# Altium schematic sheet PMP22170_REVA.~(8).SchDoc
size 431 x 279 mm; Date: Not shown in title block; ApprovedBy: Not shown in title block; CheckedBy: Not shown in title block; Author: Not shown in title block; CompanyName: Not shown in title block; Engineer: Not shown in title block; Organization: Not shown in title block; Address1: Not shown in title block; Address2: Not shown in title block; Address3: Not shown in title block; Address4: Not shown in title block; DocumentNumber: 1; Revision: Use project parameter SCH_Rev; SheetNumber: 1; SheetTotal: 1; PageSetup: Record=PageOptions¦CenterHorizontal=True¦CenterVertical=True¦PrintScale=1.00¦XCorrection=1.00¦YCorrection=1.00¦PrintKind=0¦BorderSize=5000000¦LeftOffset=0¦BottomOffset=0¦Orientation=2¦PaperLength=1000¦PaperWidth=1000¦Scale=100¦PaperSource=15¦PrintQuality=600¦MediaType=1¦DitherType=10¦PaperKind=Letter¦PrintScaleMode=1
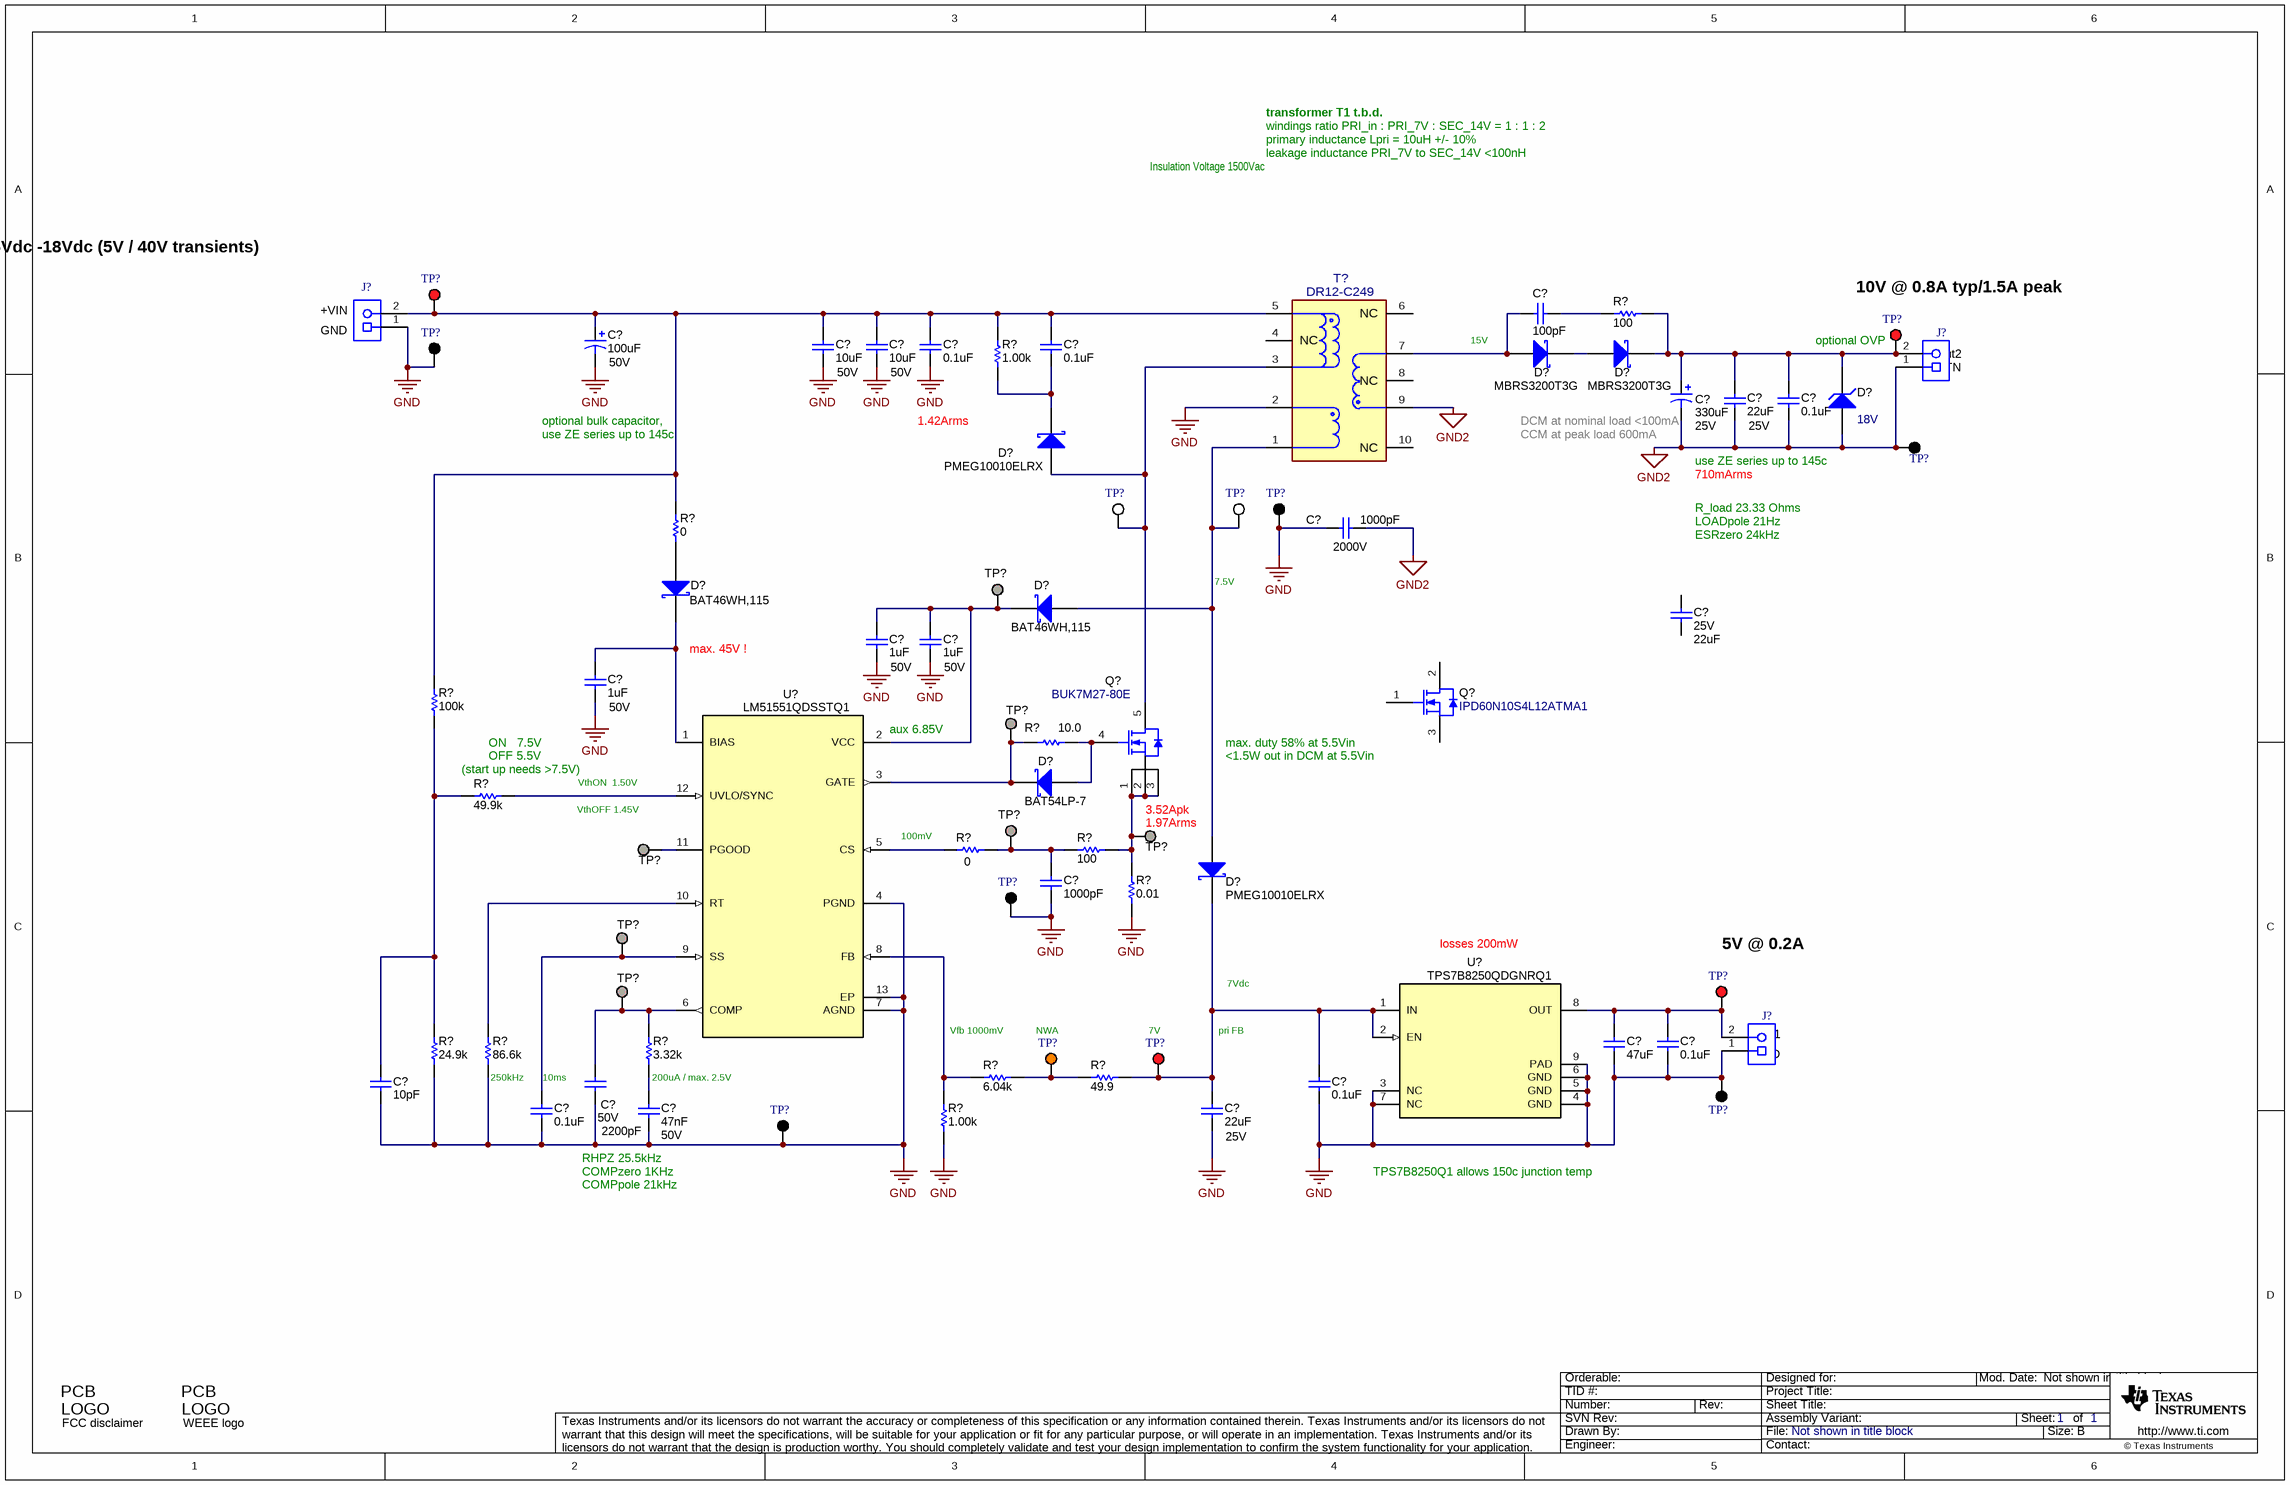
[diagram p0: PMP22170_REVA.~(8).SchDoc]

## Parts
(Parts that share a designator on the sheet are numbered #1, #2 ... from top to bottom, then left to right.)
C?#1  ValueDisplayed: 100pF  [0805_HV]  (hidden comment: Capacitor)
C?#2  ValueDisplayed: 100uF  Value2: 50V  [Panasonic_G]  (hidden comment: Cap_Polarized)
C?#3  ValueDisplayed: 10uF  Value2: 50V  [1210_270]  (hidden comment: Capacitor)
C?#4  ValueDisplayed: 10uF  Value2: 50V  [1210_270]  (hidden comment: Capacitor)
C?#5  ValueDisplayed: 0.1uF  [0603]  (hidden comment: Capacitor)
C?#6  ValueDisplayed: 0.1uF  [0603]  (hidden comment: Capacitor)
C?#7  ValueDisplayed: 330uF  Value2: 25V  [SM_RADIAL_10BMM]  (hidden comment: Cap_Polarized)
C?#8  ValueDisplayed: 22uF  Value2: 25V  [1210_270]  (hidden comment: Capacitor)
C?#9  ValueDisplayed: 0.1uF  [0603]  (hidden comment: Capacitor)
C?#10  ValueDisplayed: 1000pF  Value2: 2000V  [1808]  (hidden comment: Capacitor)
C?#11  VDC_V: 25V  ValueDisplayed: 22uF  [1210_270]  (hidden comment: TMK325B7226KMHT)
C?#12  ValueDisplayed: 1uF  Value2: 50V  [0805_HV1]  (hidden comment: Capacitor)
C?#13  ValueDisplayed: 1uF  Value2: 50V  [0805_HV1]  (hidden comment: Capacitor)
C?#14  ValueDisplayed: 1uF  Value2: 50V  [0805_HV1]  (hidden comment: Capacitor)
C?#15  ValueDisplayed: 1000pF  [0603]  (hidden comment: Capacitor)
C?#16  ValueDisplayed: 47uF  [1210_270]  (hidden comment: Capacitor)
C?#17  ValueDisplayed: 0.1uF  [0603]  (hidden comment: Capacitor)
C?#18  ValueDisplayed: 10pF  [0603]  (hidden comment: Capacitor)
C?#19  VDC_V: 50V  ValueDisplayed: 2200pF  [0603]  (hidden comment: GRM188R61H222KA01D)
C?#20  ValueDisplayed: 0.1uF  [0603]  (hidden comment: Capacitor)
C?#21  ValueDisplayed: 0.1uF  [0603]  (hidden comment: Capacitor)
C?#22  Cap_F: 47nF  VDC_V: 50V  [0603]  (hidden comment: CGA3E2X7R1H473K080AA)
C?#23  ValueDisplayed: 22uF  Value2: 25V  [1210_270]  (hidden comment: Capacitor)
D?#1  PartNumber: MBRS3200T3G  [SMB]  (hidden comment: DIODE_SCHOTTKY)
D?#2  PartNumber: MBRS3200T3G  [SMB]  (hidden comment: DIODE_SCHOTTKY)
D?#3  value 18V  [SOD-123]  (hidden comment: Zener)
D?#4  PartNumber: PMEG10010ELRX  [SOD-123W]  (hidden comment: DIODE_SCHOTTKY)
D?#5  PartNumber: BAT46WH,115  [SOD-123F]  (hidden comment: DIODE_SCHOTTKY)
D?#6  PartNumber: BAT46WH,115  [SOD-123F]  (hidden comment: DIODE_SCHOTTKY)
D?#7  PartNumber: BAT54LP-7  [X1-DFN1006-2]  (hidden comment: DIODE_SCHOTTKY)
D?#8  PartNumber: PMEG10010ELRX  [SOD-123W]  (hidden comment: DIODE_SCHOTTKY)
J?#1  Receptacle_2x1  [TERM_BLK_ED555-2DS]  (value not drawn)
J?#2  Receptacle_2x1  [TERM_BLK_ED555-2DS]  (value not drawn)
J?#3  Receptacle_2x1  [TERM_BLK_ED555-2DS]  (value not drawn)
Logo?#1  FCC disclaimer  [FCC_disclaimer]  (no BOM)
Logo?#2  WEEE logo  [WEEE_Minimum]  (no BOM)
Q?#1  IPD60N10S4L12ATMA1  [DPAK]
Q?#2  BUK7M27-80E  [LFPAK33]
R?#1  ValueDisplayed: 100  [0805_HV]  (hidden comment: Resistor)
R?#2  ValueDisplayed: 1.00k  [1210]  (hidden comment: ERJ14NF1001U)
R?#3  ValueDisplayed: 0  [0603]  (hidden comment: Resistor)
R?#4  ValueDisplayed: 100k  [0603]  (hidden comment: CRCW0603100KFKEA)
R?#5  ValueDisplayed: 10.0  [0603]  (hidden comment: Resistor)
R?#6  ValueDisplayed: 49.9k  [0603]  (hidden comment: CRCW060349K9FKEA)
R?#7  ValueDisplayed: 0  [0603]  (hidden comment: Resistor)
R?#8  ValueDisplayed: 100  [0603]  (hidden comment: Resistor)
R?#9  ValueDisplayed: 0.01  [0612]  (hidden comment: ERJ-B2CFR01V)
R?#10  ValueDisplayed: 24.9k  [0603]  (hidden comment: CRCW060324K9FKEA)
R?#11  ValueDisplayed: 86.6k  [0603]  (hidden comment: Resistor)
R?#12  ValueDisplayed: 3.32k  [0603]  (hidden comment: CRCW06033K32FKEA)
R?#13  ValueDisplayed: 6.04k  [0603]  (hidden comment: Resistor)
R?#14  ValueDisplayed: 49.9  [0603]  (hidden comment: Resistor)
R?#15  ValueDisplayed: 1.00k  [0603]  (hidden comment: Resistor)
T?  DR12-C249  [FP-DR12-C249_SMT_12MM0_14MM5-MFG]
TP?#1  5000  [Keystone5000]  (value not drawn)
TP?#2  5000  [Keystone5000]  (value not drawn)
TP?#3  5001  [Keystone5001]  (value not drawn)
TP?#4  5001  [Keystone5001]  (value not drawn)
TP?#5  5002  [Keystone5002]  (value not drawn)
TP?#6  5002  [Keystone5002]  (value not drawn)
TP?#7  5001  [Keystone5001]  (value not drawn)
TP?#8  TP_SM_1MM  [TP_SM_1MM]  (value not drawn)  (no BOM)
TP?#9  TP_SM_1MM  [TP_SM_1MM]  (value not drawn)  (no BOM)
TP?#10  TP_SM_1MM  [TP_SM_1MM]  (value not drawn)  (no BOM)
TP?#11  TP_SM_1MM  [TP_SM_1MM]  (value not drawn)  (no BOM)
TP?#12  TP_SM_1MM  [TP_SM_1MM]  (value not drawn)  (no BOM)
TP?#13  5001  [Keystone5001]  (value not drawn)
TP?#14  TP_SM_1MM  [TP_SM_1MM]  (value not drawn)  (no BOM)
TP?#15  TP_SM_1MM  [TP_SM_1MM]  (value not drawn)  (no BOM)
TP?#16  5000  [Keystone5000]  (value not drawn)
TP?#17  5003  [Keystone5003]  (value not drawn)
TP?#18  5000  [Keystone5000]  (value not drawn)
TP?#19  5001  [Keystone5001]  (value not drawn)
TP?#20  5001  [Keystone5001]  (value not drawn)
U?#1  LM51551QDSSTQ1  [DSS0012C]
U?#2  TPS7B8250QDGNRQ1  [DGN0008D_N]

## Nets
GND: C?#2.2(-) C?#3.2 C?#4.2 C?#5.2 C?#10.2 C?#12.2 C?#13.2 C?#14.2 C?#15.2 C?#16.2 C?#17.2 C?#18.2 C?#19.2 C?#20.2 C?#21.2 C?#22.2 C?#23.2 J?#1.1 J?#3.1 R?#9.1 R?#10.1 R?#11.1 R?#15.2 T?.2(S3) TP?#3.1 TP?#7.1 TP?#13.1 TP?#19.1 TP?#20.1 U?#1.4(PGND) U?#1.7(AGND) U?#1.13(EP) U?#2.3(NC) U?#2.4(GND) U?#2.5(GND) U?#2.6(GND) U?#2.7(NC) U?#2.9(PAD)
GND2: C?#7.2(-) C?#8.2 C?#9.2 C?#10.1 D?#3.2(A) J?#2.1 T?.9(S4) TP?#4.1
NetC?#1_1: C?#1.1 R?#1.1
NetC?#1_2: C?#1.2 D?#1.2(A) T?.7
NetC?#2_1: C?#2.1(+) C?#3.1 C?#4.1 C?#5.1 C?#6.1 J?#1.2 R?#2.2 R?#3.2 R?#4.2 T?.5(S1,S2) TP?#1.1
NetC?#6_2: C?#6.2 D?#4.1(K) R?#2.1
NetC?#7_1: C?#7.1(+) C?#8.1 C?#9.1 D?#2.1(K) D?#3.1(K) J?#2.2 R?#1.2 TP?#2.1
NetC?#12_1: C?#12.1 C?#13.1 D?#6.1(K) TP?#8.1 U?#1.2(VCC)
NetC?#14_1: C?#14.1 D?#5.1(K) U?#1.1(BIAS)
NetC?#15_1: C?#15.1 R?#7.2 R?#8.1 TP?#10.1
NetC?#16_1: C?#16.1 C?#17.1 J?#3.2 TP?#16.1 U?#2.8(OUT)
NetC?#18_1: C?#18.1 R?#4.1 R?#6.1 R?#10.2
NetC?#19_1: C?#19.1 R?#12.2 TP?#15.1 U?#1.6(COMP)
NetC?#20_1: C?#20.1 C?#23.1 D?#8.1(K) R?#14.2 TP?#18.1 U?#2.1(IN) U?#2.2(EN)
NetC?#21_1: C?#21.1 TP?#14.1 U?#1.9(SS)
NetC?#22_1: C?#22.1 R?#12.1
NetD?#1_1: D?#1.1(K) D?#2.2(A)
NetD?#4_2: D?#4.2(A) Q?#2.5(D) T?.3 TP?#5.1
NetD?#5_2: D?#5.2(A) R?#3.1
NetD?#6_2: D?#6.2(A) D?#8.2(A) T?.1 TP?#6.1
NetD?#7_1: D?#7.1(K) R?#5.1 TP?#9.1 U?#1.3(GATE)
NetD?#7_2: D?#7.2(A) Q?#2.4(G) R?#5.2
NetQ?#2_1: Q?#2.1(S) Q?#2.2(S) Q?#2.3(S) R?#8.2 R?#9.2 TP?#11.1
NetR?#6_2: R?#6.2 U?#1.12(UVLO/SYNC)
NetR?#7_1: R?#7.1 U?#1.5(CS)
NetR?#11_2: R?#11.2 U?#1.10(RT)
NetR?#13_1: R?#13.1 R?#14.1 TP?#17.1
NetR?#13_2: R?#13.2 R?#15.1 U?#1.8(FB)
NetTP?#12_1: TP?#12.1 U?#1.11(PGOOD)

Not connected (* = marked no-connect by the designer): C?#11 1 2; Q?#1 1(G) 2(D) 3(S); T? 4(NC) 6(NC) 8(NC) 10(NC)

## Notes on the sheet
- Insulation Voltage 1500Vac
- windings ratio PRI_in : PRI_7V : SEC_14V = 1 : 1 : 2
- primary inductance Lpri = 10uH +/- 10%
- leakage inductance PRI_7V to SEC_14V <100nH
- transformer T1 t.b.d.
- Input 6Vdc -18Vdc (5V / 40V transients)
- 10V @ 0.8A typ/1.5A peak
- (near J?#1) +VIN
- (near J?#1) GND
- 15V
- (near TP?#2) optional OVP
- (near J?#2) Vout2
- (near J?#2) RTN
- optional bulk capacitor,
- use ZE series up to 145c
- 1.42Arms
- (near C?#7) CCM at peak load 600mA
- (near C?#7) DCM at nominal load <100mA
- (near C?#9) use ZE series up to 145c
- 710mArms
- R_load 23.33 Ohms
- LOADpole 21Hz
- ESRzero 24kHz
- 7.5V
- (near D?#5) max. 45V !
- (near R?#6) (start up needs >7.5V)
- (near R?#6) ON   7.5V
- (near R?#6) OFF 5.5V
- (near U?#1) aux 6.85V
- (near Q?#1) max. duty 58% at 5.5Vin
- (near Q?#1) <1.5W out in DCM at 5.5Vin
- VthON  1.50V
- (near TP?#12) VthOFF 1.45V
- 100mV
- 3.52Apk
- (near TP?#11) 1.97Arms
- losses 200mW
- (near TP?#16) 5V @ 0.2A
- Vfb 1000mV
- (near TP?#17) NWA
- (near TP?#18) 7V
- pri FB
- 7Vdc
- (near J?#3) Vout1
- (near R?#11) 250kHz
- (near C?#21) 10ms
- (near R?#12) 200uA / max. 2.5V
- (near J?#3) GND
- (near C?#22) RHPZ 25.5kHz
- (near C?#22) COMPzero 1KHz
- TPS7B8250Q1 allows 150c junction temp
- COMPpole 21kHz

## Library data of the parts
C?#1 = CMP-0008236-2: CAP, CERM, 100 pF, 250 V, +/- 5%, C0G/NP0, 0805; PartNumber: GRM21A5C2E101JW01D; Manufacturer: MuRata; Polarized: N; Value: 100pF; U/M: EA; Value1: Unknown; VDC_V: 250V; TaMin_C: -55°C; TaMax_C: 125°C; Cap_Case: 0805; SizeArea_mm2: 2.5; SizeAreaWB_mm2: 6.75; SizeX_mm: 2; SizeY_mm: 1.25; SizeZ_mm: 1.45; AEC Category: Q200
C?#2 = CMP-0064994-2: CAP, Polymer Hybrid, 100 uF, 50 V,+/- 20%, 0.028 ohm, AEC-Q200 Grade 1, D10xL10.2mm SMD; PartNumber: EEH-ZC1H101P; Manufacturer: Panasonic; Polarized: Y; CompType: Capacitor; Value: 100uF; Cap_F: 100µF; ESR_ohm: 0.028; IRMS_A: 1.6A; TaMin_C: -55°C; TaMax_C: 125°C; Cap_Case: 10x10.2mm; SizeAreaWB_mm2: 151.29; SizeArea_mm2: 106.09; SizeX_mm: 10.3; SizeZ_mm: 10.5; AEC Category: Q200; AEC Grade: 1
C?#3 C?#4 = CMP-0009226-3: CAP, CERM, 10 uF, 50 V, +/- 10%, X7R, 1210; PartNumber: GRM32ER71H106KA12L; Manufacturer: MuRata; Polarized: N; Value: 10uF; U/M: EA; Cap_F: 10µF; Value1: Unknown; TaMin_C: -55°C; TaMax_C: 125°C; Cap_Case: 1210; SizeArea_mm2: 8; SizeAreaWB_mm2: 14.7; SizeX_mm: 3.2; SizeY_mm: 2.5; SizeZ_mm: 2.7; AEC Category: Q200
C?#5 C?#6 C?#9 = CMP-0007144-4: CAP, CERM, 0.1 uF, 50 V, +/- 10%, X7R, 0603; PartNumber: GCM188R71H104KA57D; Manufacturer: MuRata; Polarized: N; Value: 0.1uF; U/M: EA; Cap_F: 100nF; ESR_ohm: 0.02; Value1: 0.02 ohm; VDC_V: 50V; IRMS_A: 1.84A; TaMin_C: -55°C; TaMax_C: 125°C; AEC Category: Q200; SizeArea_mm2: 1.28; SizeAreaWB_mm2: 4.68; SizeX_mm: 1.6; SizeY_mm: 0.8; SizeZ_mm: 1
C?#7 = CMP-0012593-3: CAP, Polymer Hybrid, 330 uF, 25 V, +/- 20%, 20 ohm, 10x10 SMD; PartNumber: EEHZC1E331P; Manufacturer: Panasonic; Polarized: Y; CompType: Capacitor; Value: 330uF; Cap_F: 330µF; Value1: 20 ohm; ESR_ohm: 20; IRMS_A: 2A; TaMin_C: -55°C; TaMax_C: 125°C; SizeAreaWB_mm2: 159.9; SizeArea_mm2: 113.3; SizeX_mm: 11; SizeY_mm: 10.3; SizeZ_mm: 10.2; AEC Category: Q200
C?#8 C?#23 = CMP-0009224-2: CAP, CERM, 22 uF, 25 V, +/- 10%, X7R, 1210; PartNumber: GRM32ER71E226KE15L; Manufacturer: MuRata; Polarized: N; Value: 22uF; U/M: EA; Cap_F: 22µF; Value1: Unknown; TaMin_C: -55°C; TaMax_C: 125°C; Cap_Case: 1210; SizeArea_mm2: 8; SizeAreaWB_mm2: 14.7; SizeX_mm: 3.2; SizeY_mm: 2.5; SizeZ_mm: 2.7; AEC Category: Q200
C?#10 = CMP-0009436-2: CAP, CERM, 1000 pF, 2000 V, +/- 10%, X7R, 1808; PartNumber: GR442QR73D102KW01L; Manufacturer: MuRata; Polarized: N; Value: 1000pF; U/M: EA; Cap_F: 1nF; Value1: Unknown; VDC_V: 2kV; TaMin_C: -55°C; TaMax_C: 125°C; SizeArea_mm2: 9; SizeAreaWB_mm2: 16.5; SizeX_mm: 4.5; SizeY_mm: 2; SizeZ_mm: 2.03; AEC Category: Q200
C?#11 = CMP-0009255-2: CAP, CERM, 22 uF, 25 V, +/- 10%, X7R, AEC-Q200 Grade 1, 1210; Manufacturer: Taiyo Yuden; TaMin_C: -55°C; Polarized: N; SizeAreaWB_mm2: 14.7; Value1: Unknown; U/M: EA; Value: 22uF; TaMax_C: 125°C; SizeZ_mm: 2.7; SizeX_mm: 3.2; SizeY_mm: 2.5; Cap_Case: 1210; SizeArea_mm2: 8; AEC Qualified: Y; Cap_F: 22µF; AEC Grade: 1; AEC Category: Q200
C?#12-C?#14 = CMP-0008350-2: CAP, CERM, 1 uF, 50 V, +/- 10%, X7R, 0805; PartNumber: GRM21BR71H105KA12L; Manufacturer: MuRata; Polarized: N; Value: 1uF; U/M: EA; Cap_F: 1µF; Value1: Unknown; TaMin_C: -55°C; TaMax_C: 125°C; Cap_Case: 0805; SizeArea_mm2: 2.5; SizeAreaWB_mm2: 6.75; SizeX_mm: 2; SizeY_mm: 1.25; SizeZ_mm: 1.45; AEC Category: Q200
C?#15 = CMP-0007402-4: CAP, CERM, 1000 pF, 25 V, +/- 10%, X7R, 0603; PartNumber: GRM188R71E102KA01D; Manufacturer: MuRata; Polarized: N; Value: 1000pF; U/M: EA; Cap_F: 1nF; Value1: Unknown; VDC_V: 25V; TaMin_C: -55°C; TaMax_C: 125°C; SizeArea_mm2: 1.28; SizeAreaWB_mm2: 4.68; SizeX_mm: 1.6; SizeY_mm: 0.8; SizeZ_mm: 1; AEC Category: Q200
C?#16 = CMP-0009220-2: CAP, CERM, 47 uF, 10 V, +/- 10%, X7R, 1210; PartNumber: GRM32ER71A476KE15L; Manufacturer: MuRata; Polarized: N; Value: 47uF; U/M: EA; Cap_F: 47µF; Value1: Unknown; VDC_V: 10V; TaMin_C: -55°C; TaMax_C: 125°C; Cap_Case: 1210; SizeArea_mm2: 8; SizeAreaWB_mm2: 14.7; SizeX_mm: 3.2; SizeY_mm: 2.5; SizeZ_mm: 2.7; AEC Category: Q200
C?#17 C?#20 C?#21 = CMP-0007378-5: CAP, CERM, 0.1 uF, 16 V, +/- 10%, X7R, 0603; PartNumber: GRM188R71C104KA01D; Manufacturer: MuRata; Polarized: N; Value: 0.1uF; U/M: EA; Cap_F: 100nF; Value1: Unknown; VDC_V: 16V; TaMin_C: -55°C; TaMax_C: 125°C; SizeArea_mm2: 1.28; SizeAreaWB_mm2: 4.68; SizeX_mm: 1.6; SizeY_mm: 0.8; SizeZ_mm: 1; AEC Category: Q200
C?#18 = CMP-0007170-4: CAP, CERM, 10 pF, 50 V, +/- 5%, C0G/NP0, 0603; PartNumber: GRM1885C1H100JA01D; Manufacturer: MuRata; Polarized: N; Value: 10pF; U/M: EA; Value1: Unknown; VDC_V: 50V; TaMin_C: -55°C; TaMax_C: 125°C; SizeArea_mm2: 1.28; SizeAreaWB_mm2: 4.68; SizeX_mm: 1.6; SizeY_mm: 0.8; SizeZ_mm: 1; AEC Category: Q200
C?#19 = CMP-0007351-3: CAP, CERM, 2200 pF, 50 V, +/- 10%, X5R, 0603; Manufacturer: MuRata; TaMin_C: -55°C; Polarized: N; SizeAreaWB_mm2: 4.68; Value1: Unknown; U/M: EA; Value: 2200pF; TaMax_C: 85°C; SizeZ_mm: 1; SizeX_mm: 1.6; SizeY_mm: 0.8; SizeArea_mm2: 1.28; Cap_F: 2.2nF; AEC Category: Q200
C?#22 = CMP-0007079-4: CAP, CERM, 0.047 uF, 50 V, +/- 10%, X7R, AEC-Q200 Grade 1, 0603; Manufacturer: TDK; TaMin_C: -55°C; ESR_ohm: 0.049007; Polarized: N; SizeAreaWB_mm2: 4.68; Value1: 0.049007 ohm; U/M: EA; TaMax_C: 125°C; SizeZ_mm: 1; SizeX_mm: 1.6; SizeY_mm: 0.8; SizeArea_mm2: 1.28; AEC Qualified: Y; IRMS_A: 767.528mA; AEC Category: Q200
D?#1 D?#2 = CMP-0028599-2: Diode, Schottky, 200 V, 3 A, SMB; Manufacturer: ON Semiconductor; Vf_V: 840mV; Value: 200V; Value1: 3A; Value2: 0.84V; TJmax_C: 175°C; RJC_CperW: 62; SizeAreaWB_mm2: 44.156; SizeArea_mm2: 21.336; SizeX_mm: 5.6; SizeY_mm: 3.81; SizeZ_mm: 2.6; AEC Category: Q101; Green_Lifecycle: Not Set; Green_REACh: Incomplete
D?#3 = CMP-0005755-4: Diode, Zener, 18 V, 500 mW, SOD-123; PartNumber: MMSZ5248B-7-F; Manufacturer: Diodes Inc.; Power_W: 500mW; Value1: 0.5W; RJA_CperW: 350; SizeAreaWB_mm2: 13.095; SizeArea_mm2: 6.545; SizeX_mm: 3.85; SizeY_mm: 1.7; SizeZ_mm: 1.35; AEC Category: Q101
D?#4 D?#8 = CMP-0028782-2: Diode, Schottky, 100 V, 1 A, AEC-Q101, SOD-123W; Manufacturer: Nexperia; Vf_V: 770mV; Value: 100V; Value1: 1A; Value2: 0.77V; TJmax_C: 175°C; SizeAreaWB_mm2: 12.15; SizeArea_mm2: 5.95; SizeX_mm: 3.5; SizeY_mm: 1.7; SizeZ_mm: 1; AEC Category: Q101; AEC Qualified: Y; Green_Lifecycle: Not Set; Green_REACh: Incomplete
D?#5 D?#6 = CMP-0028632-2: Diode, Schottky, 100 V, 0.25 A, SOD-123F; Manufacturer: Nexperia; Vf_V: 850mV; Value: 100V; Value1: 0.25A; Value2: 0.85V; Io_A: 250mA; TJmax_C: 150°C; SizeAreaWB_mm2: 11.7; SizeArea_mm2: 5.6; SizeX_mm: 3.5; SizeY_mm: 1.6; SizeZ_mm: 1.1; AEC Category: Q101; Green_Lifecycle: Not Set; Green_REACh: Incomplete
D?#7 = CMP-0076931-2: Diode, Schottky, 30 V, 0.2 A, 1.00x0.50x0.60mm; Manufacturer: Diodes Inc.; Vf_V: 1V; Value: 30V; Value1: 0.2A; Io_A: 200mA; SizeAreaWB_mm2: 3.2; SizeArea_mm2: 0.6; SizeX_mm: 1.0; SizeZ_mm: 0.53; AEC Category: Q101; Green_Lifecycle: Not Set; Green_REACh: Incomplete
J?#1-J?#3 = CMP-0074913-1: Terminal Block, 3.5mm Pitch, 2x1, TH; PartNumber: ED555/2DS; Manufacturer: On-Shore Technology; Cert_CULUS: Y; CNHeader: False; ContactFinish: Brass; CT: True; Current_A: 6A; Gender: Female; Green_Lifecycle: Active; Green_REACh: Passed; Pitch_mm: 3.5; Row_Count: 1; Shrouded: N; Voltage_V: 150V
Logo?#1 = CMP-0074847-1: FCC_disclaimer; Library Reference: Logo
Logo?#2 = CMP-0074769-1
Q?#1 = CMP-0080670-2: MOSFET, N-CH, 100 V, 60 A, AEC-Q101, DPAK; Manufacturer: Infineon Technologies; Alternate Manufacturer: None; QgTyp_nC: 38; AEC Category: Q101; Vgs_V: 16V; Value1: 0.015 ohm; SizeAreaWB_mm2: 101.7114; IdsMax_A: 60A; SizeX_mm: 9.91; SizeArea_mm2: 64.8114; Value: 100V; Value2: 38 nC; Rdson45_ohm: 0.015; SizeY_mm: 6.54; ChType: N; AEC Qualified: Y; ChMode: Enhancement; SizeZ_mm: 2.29
Q?#2 = CMP-0000806-3: MOSFET, N-CH, 80 V, 30 A, AEC-Q101, 3.4x0.9x2.7mm; Alternate Manufacturer: None; Manufacturer: Nexperia; SizeZ_mm: 0.9; ChType: N; Value2: 19.5 nC; VdsMax_V: 80V; SizeX_mm: 3.3; Vgs_V: 20V; QgTyp_nC: 19.5; AEC Qualified: Y; Value: 80V; SizeArea_mm2: 10.89; AEC Category: Q101; IdsMax_A: 30A; SizeAreaWB_mm2: 18.49
R?#1 = CMP-0020445-3: RES, 100, 5%, 0.125 W, AEC-Q200 Grade 0, 0805; PartNumber: CRCW0805100RJNEA; Manufacturer: Vishay-Dale; Value: 100; Value_Code: 100R; Power_W: 125mW; Value2: 0.125W; VDC_V: 150V; TempCo: 200 ppm/C; SizeArea_mm2: 2.5; SizeX_mm: 2; SizeY_mm: 1.25; SizeZ_mm: 1.45; EIA_Code: E24; AEC Category: Q200; AEC Qualified: Y; AEC Grade: 0
R?#2 = CMP-0015030-3: RES, 1.00 k, 1%, 0.5 W, AEC-Q200 Grade 0, 1210; Manufacturer: Panasonic; Power_W: 500mW; TempCo: 100 ppm/C; SizeAreaWB_mm2: 14.7; Value_Code: 1k00; Value: 1.00k; EIA_Code: E96; Res_ohm: 1k; SizeX_mm: 3.2; SizeY_mm: 2.5; SizeZ_mm: 1.35; Value2: 0.5W; SizeArea_mm2: 8; AEC Qualified: Y; VDC_V: 22V; AEC Category: Q200; AEC Grade: 0
R?#3 R?#7 = CMP-0025697-4: RES, 0, 5%, 0.1 W, AEC-Q200 Grade 0, 0603; PartNumber: CRCW06030000Z0EA; Manufacturer: Vishay-Dale; Value: 0; Value_Code: 0000; Power_W: 100mW; Value2: 0.1W; VDC_V: 75V; TempCo: 200 ppm/C; SizeArea_mm2: 1.28; SizeX_mm: 1.6; SizeY_mm: 0.8; SizeZ_mm: 1; EIA_Code: E24; AEC Category: Q200; AEC Qualified: Y
R?#4 = CMP-0021990-4: RES, 100 k, 1%, 0.1 W, AEC-Q200 Grade 0, 0603; Manufacturer: Vishay-Dale; Power_W: 100mW; TempCo: 100 ppm/C; Value: 100k; EIA_Code: E96; SizeX_mm: 1.6; SizeY_mm: 0.8; SizeZ_mm: 1; Value2: 0.1W; SizeArea_mm2: 1.28; AEC Qualified: Y; VDC_V: 75V; AEC Category: Q200; AEC Grade: 0
R?#5 = CMP-0022003-4: RES, 10.0, 1%, 0.1 W, AEC-Q200 Grade 0, 0603; PartNumber: CRCW060310R0FKEA; Manufacturer: Vishay-Dale; Value: 10.0; Res_ohm: 10; Value_Code: 10R0; Power_W: 100mW; Value2: 0.1W; VDC_V: 75V; TempCo: 100 ppm/C; SizeArea_mm2: 1.28; SizeX_mm: 1.6; SizeY_mm: 0.8; SizeZ_mm: 1; EIA_Code: E96; AEC Category: Q200; AEC Qualified: Y; AEC Grade: 0
R?#6 = CMP-0022447-4: RES, 49.9 k, 1%, 0.1 W, AEC-Q200 Grade 0, 0603; Manufacturer: Vishay-Dale; Power_W: 100mW; TempCo: 100 ppm/C; Value_Code: 49k9; Value: 49.9k; EIA_Code: E96; SizeX_mm: 1.6; SizeY_mm: 0.8; SizeZ_mm: 1; Value2: 0.1W; SizeArea_mm2: 1.28; AEC Qualified: Y; VDC_V: 75V; AEC Category: Q200; AEC Grade: 0
R?#8 = CMP-0021991-4: RES, 100, 1%, 0.1 W, AEC-Q200 Grade 0, 0603; PartNumber: CRCW0603100RFKEA; Manufacturer: Vishay-Dale; Value: 100; Value_Code: 100R; Power_W: 100mW; Value2: 0.1W; VDC_V: 75V; TempCo: 100 ppm/C; SizeArea_mm2: 1.28; SizeX_mm: 1.6; SizeY_mm: 0.8; SizeZ_mm: 1; EIA_Code: E96; AEC Category: Q200; AEC Qualified: Y; AEC Grade: 0
R?#9 = CMP-0015054-2: RES, 0.01, 1%, 1 W, AEC-Q200 Grade 0, 0612; Manufacturer: Panasonic; Power_W: 1W; TempCo: 300 ppm/C; SizeAreaWB_mm2: 10.92; Value_Code: R010; U/M: EA; Value: 0.01; EIA_Code: E96; SizeX_mm: 1.6; SizeY_mm: 3.2; SizeZ_mm: 0.85; SizeArea_mm2: 5.12; AEC Qualified: Y; AEC Grade: 0; AEC Category: Q200
R?#10 = CMP-0022237-4: RES, 24.9 k, 1%, 0.1 W, AEC-Q200 Grade 0, 0603; Manufacturer: Vishay-Dale; Power_W: 100mW; TempCo: 100 ppm/C; Value_Code: 24k9; Value: 24.9k; EIA_Code: E96; SizeX_mm: 1.6; SizeY_mm: 0.8; SizeZ_mm: 1; Value2: 0.1W; SizeArea_mm2: 1.28; AEC Qualified: Y; VDC_V: 75V; AEC Category: Q200; AEC Grade: 0
R?#11 = CMP-0022628-4: RES, 86.6 k, 1%, 0.1 W, AEC-Q200 Grade 0, 0603; PartNumber: CRCW060386K6FKEA; Manufacturer: Vishay-Dale; Value: 86.6k; Value_Code: 86k6; Power_W: 100mW; Value2: 0.1W; VDC_V: 75V; TempCo: 100 ppm/C; SizeArea_mm2: 1.28; SizeX_mm: 1.6; SizeY_mm: 0.8; SizeZ_mm: 1; EIA_Code: E96; AEC Category: Q200; AEC Qualified: Y; AEC Grade: 0
R?#12 = CMP-0022375-4: RES, 3.32 k, 1%, 0.1 W, AEC-Q200 Grade 0, 0603; Manufacturer: Vishay-Dale; Power_W: 100mW; TempCo: 100 ppm/C; Value_Code: 3k32; Value: 3.32k; EIA_Code: E96; SizeX_mm: 1.6; SizeY_mm: 0.8; Value2: 0.1W; SizeArea_mm2: 1.28; AEC Qualified: Y; VDC_V: 75V; AEC Category: Q200; SizeZ_mm: 1; AEC Grade: 0
R?#13 = CMP-0022558-4: RES, 6.04 k, 1%, 0.1 W, AEC-Q200 Grade 0, 0603; PartNumber: CRCW06036K04FKEA; Manufacturer: Vishay-Dale; Value: 6.04k; Value_Code: 6k04; Power_W: 100mW; Value2: 0.1W; VDC_V: 75V; TempCo: 100 ppm/C; SizeArea_mm2: 1.28; SizeX_mm: 1.6; SizeY_mm: 0.8; SizeZ_mm: 1; EIA_Code: E96; AEC Category: Q200; AEC Qualified: Y; AEC Grade: 0
R?#14 = CMP-0022448-4: RES, 49.9, 1%, 0.1 W, AEC-Q200 Grade 0, 0603; PartNumber: CRCW060349R9FKEA; Manufacturer: Vishay-Dale; Value: 49.9; Value_Code: 49R9; Power_W: 100mW; Value2: 0.1W; VDC_V: 75V; TempCo: 100 ppm/C; SizeArea_mm2: 1.28; SizeX_mm: 1.6; SizeY_mm: 0.8; SizeZ_mm: 1; EIA_Code: E96; AEC Category: Q200; AEC Qualified: Y; AEC Grade: 0
R?#15 = CMP-0022109-5: RES, 1.00 k, 1%, 0.1 W, AEC-Q200 Grade 0, 0603; PartNumber: CRCW06031K00FKEA; Manufacturer: Vishay-Dale; Value: 1.00k; Res_ohm: 1k; Value_Code: 1k00; Power_W: 100mW; Value2: 0.1W; VDC_V: 75V; TempCo: 100 ppm/C; EIA_Code: E96; AEC Category: Q200; AEC Grade: 0; AEC Qualified: Y; SizeArea_mm2: 1.28; SizeX_mm: 1.6; SizeY_mm: 0.8; SizeZ_mm: 1
T? = CMP-0087431-1: TRANSFORMER; Manufacturer: Mitsumi Electric; Ind_H: 12µH; Rsec1_ohm: 0.1; AEC Qualified: No; SizeZ_mm: 6.8mm
TP?#1 TP?#2 TP?#16 TP?#18 = CMP-0055137-1: Test Point, Miniature, Red, TH; Manufacturer: Keystone; CNHeader: FALSE; ContactFinish: Silver; CT: TRUE; Green_Lifecycle: Active; Green_REACh: Passed
TP?#3 TP?#4 TP?#7 TP?#13 TP?#19 TP?#20 = CMP-0055138-1: Test Point, Miniature, Black, TH; Manufacturer: Keystone; CNHeader: FALSE; ContactFinish: Silver; CT: TRUE; Green_Lifecycle: Active; Green_REACh: Passed
TP?#5 TP?#6 = CMP-0055139-1: Test Point, Miniature, White, TH; Manufacturer: Keystone; ContactFinish: Silver; CNHeader: FALSE; CT: TRUE; Green_Lifecycle: Active; Green_REACh: Passed
TP?#8-TP?#12 TP?#14 TP?#15 = CMP-0003825-1: 1mm Test Point, SMT; Manufacturer: Any
TP?#17 = CMP-0055140-1: Test Point, Miniature, Orange, TH; Manufacturer: Keystone; ContactFinish: Silver; CNHeader: FALSE; CT: TRUE; Green_Lifecycle: Active; Green_REACh: Passed
U?#1 = CMP-0081540-1: Automotive Grade 2.2-MHz Wide Input Non-synchronous Boost Controller, DSS0012C (WSON-12); Alternate PartNumber: LM51551QDSSRQ1; Alternate Manufacturer: Texas Instruments; SizeAreaWB_mm2: 12; SizeZ_mm: 0.8; SizeX_mm: 2; SizeY_mm: 3; SizeArea_mm2: 6; CompType: IC; AEC Qualified: Y; AEC Category: Q200
U?#2 = CMP-0013313-4: 300mA High-Voltage Ultra-Low-Iq Low-Dropout (LDO) Regulator, DGN0008D (VSSOP-8); Manufacturer: Texas Instruments; SizeX_mm: 5.05; SizeY_mm: 3.1; CompType: IC; SizeZ_mm: 1.1; SizeArea_mm2: 15.655; SizeAreaWB_mm2: 35.955; AEC Category: Q200; AEC Qualified: Y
